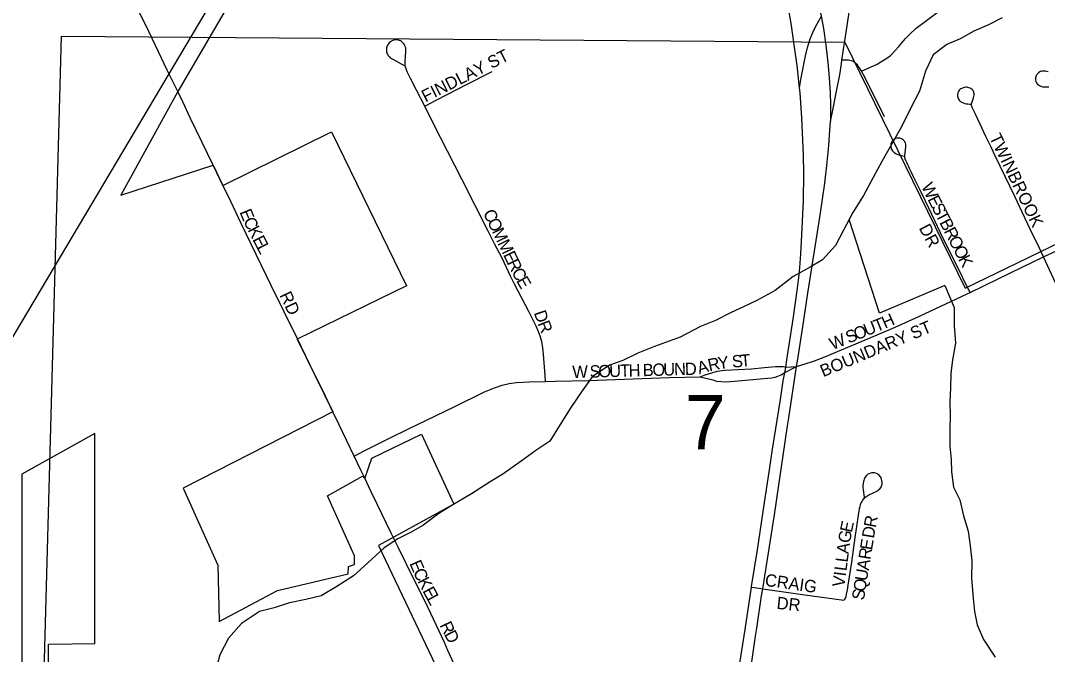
# Model space of a CAD drawing. Extents: x -5.6 to 34, y 0 to 22.
# Drawn here: x 3.152 to 4.822, y 19.057 to 20.089 of the extents above; entities that cross this region are included whole.
import ezdxf

# ---------------------------------------------------------------- set-up
doc = ezdxf.new("R2010")
doc.units = 0
for name, color, linetype in [('GM_X_City_Street', 7, 'Continuous'), ('GM_X_City_Street_Text', 7, 'Continuous'), ('GM_X_Corporation', 7, 'Continuous'), ('GM_X_Minor_River', 7, 'Continuous'), ('GM_X_Rail_Line', 7, 'Continuous'), ('GM_X_Section', 7, 'Continuous'), ('GM_X_Section_Text', 7, 'Continuous'), ('GM_X_State_Route', 7, 'Continuous'), ('GM_X_Township_Road', 7, 'Continuous')]:
    doc.layers.add(name, color=color, linetype=linetype)

msp = doc.modelspace()

# ---------------------------------------------------------------- linework, layer by layer
at = {"layer": 'GM_X_City_Street'}
for points in [[(3.4074, 19.9733), (3.3902, 20.0079), (3.3759, 20.0378), (3.3552, 20.0811), (3.3122, 20.168), (3.2939, 20.2059), (3.2812, 20.2325)], [(4.4957, 20.0768), (4.5106, 20.1745), (4.5139, 20.1982)], [(4.5198, 20.0063), (4.5448, 20.0181), (4.5512, 20.0216), (4.5567, 20.025), (4.5639, 20.03), (4.5671, 20.0325), (4.5698, 20.035), (4.5743, 20.0398), (4.5802, 20.0466), (4.591, 20.0594), (4.5974, 20.066), (4.6087, 20.0762), (4.623, 20.087), (4.6533, 20.1103)], [(4.4187, 19.9793), (4.4216, 19.9958), (4.4283, 20.0312), (4.4317, 20.045), (4.4361, 20.0589), (4.4405, 20.0696), (4.4447, 20.0787), (4.4499, 20.0884), (4.4544, 20.0959)], [(4.4878, 20.0245), (4.4947, 20.0699), (4.4957, 20.0768)], [(3.809, 19.9496), (3.7956, 19.9757), (3.7859, 19.9944), (3.7806, 20.0051), (3.7787, 20.0102), (3.778, 20.0128), (3.7774, 20.0155), (3.777, 20.0188), (3.777, 20.0223), (3.7779, 20.0318), (3.7785, 20.0369), (3.7785, 20.0419), (3.7781, 20.0443), (3.7775, 20.0466), (3.7765, 20.0489), (3.7753, 20.0507), (3.7742, 20.0521), (3.7731, 20.0533), (3.7713, 20.0548), (3.7696, 20.0558), (3.7682, 20.0564), (3.7666, 20.0569), (3.7649, 20.0573), (3.7634, 20.0574), (3.7615, 20.0574), (3.7597, 20.0572), (3.758, 20.0567), (3.7549, 20.0552), (3.752, 20.0531), (3.7497, 20.0505), (3.7486, 20.0489), (3.7479, 20.0474), (3.7473, 20.0459), (3.7469, 20.0442), (3.7466, 20.0424), (3.7466, 20.0407), (3.7468, 20.0388), (3.7471, 20.0373), (3.7476, 20.0356), (3.7483, 20.0341), (3.7492, 20.0326), (3.7504, 20.0311), (3.7516, 20.0298), (3.753, 20.0284), (3.7572, 20.0258), (3.7758, 20.0158)], [(4.4693, 19.9243), (4.4736, 19.9459), (4.4797, 19.9764), (4.4842, 20.0006), (4.4868, 20.0184), (4.4878, 20.0245)], [(4.5198, 20.0063), (4.5191, 20.0076), (4.5164, 20.012), (4.5144, 20.0148), (4.5128, 20.0167), (4.511, 20.0186), (4.5091, 20.0202), (4.507, 20.0216), (4.505, 20.0226), (4.503, 20.0233), (4.5006, 20.0238), (4.4982, 20.0241), (4.4957, 20.0242), (4.4878, 20.0245)], [(3.809, 19.9496), (3.8276, 19.9591), (3.879, 19.9857), (3.919, 20.0059)], [(4.5572, 19.9319), (4.5257, 19.9955), (4.5198, 20.0063)], [(4.823, 20.0051), (4.8211, 20.0058), (4.8189, 20.0063), (4.8165, 20.0066), (4.8148, 20.0066), (4.8131, 20.0063), (4.8109, 20.0057), (4.808, 20.0041), (4.8066, 20.0029), (4.8055, 20.0017), (4.8045, 20.0005), (4.8036, 19.9988), (4.803, 19.9974), (4.8027, 19.9956), (4.8026, 19.9934), (4.8027, 19.9918), (4.8032, 19.9894), (4.8042, 19.9874), (4.8059, 19.9854), (4.8073, 19.9843), (4.8089, 19.9832), (4.8112, 19.982), (4.814, 19.9812), (4.8168, 19.981), (4.8209, 19.9809), (4.8245, 19.9812)], [(4.8157, 19.7041), (4.8089, 19.7184), (4.7946, 19.748), (4.7808, 19.7768), (4.7693, 19.8013), (4.7531, 19.835), (4.7371, 19.8685), (4.7303, 19.8828), (4.722, 19.8999), (4.7125, 19.9203), (4.7051, 19.9362), (4.6992, 19.9482), (4.6988, 19.9496), (4.6987, 19.9513), (4.6987, 19.9535), (4.699, 19.955), (4.7019, 19.9631), (4.7024, 19.9654), (4.7027, 19.9676), (4.7027, 19.9693), (4.7025, 19.971), (4.7021, 19.9725), (4.7018, 19.9736), (4.701, 19.975), (4.7001, 19.9762), (4.6989, 19.9773), (4.6975, 19.9782), (4.6961, 19.9789), (4.6943, 19.9795), (4.6927, 19.98), (4.6906, 19.9802), (4.6891, 19.9802), (4.6873, 19.9799), (4.6839, 19.979), (4.6823, 19.9784), (4.6808, 19.9775), (4.6795, 19.9764), (4.6785, 19.9753), (4.6775, 19.9738), (4.6769, 19.9727), (4.6763, 19.9709), (4.6759, 19.9692), (4.6759, 19.9674), (4.6759, 19.9658), (4.6763, 19.964), (4.6768, 19.9623), (4.6776, 19.9608), (4.6786, 19.9593), (4.6797, 19.9582), (4.681, 19.9569), (4.6824, 19.956), (4.6839, 19.9552), (4.6852, 19.9547), (4.6866, 19.9542), (4.6879, 19.9538), (4.6899, 19.9535), (4.6924, 19.9532), (4.695, 19.953), (4.6965, 19.9529), (4.6978, 19.953)], [(3.4649, 19.8535), (3.4378, 19.9092), (3.428, 19.9296), (3.4154, 19.9564), (3.4074, 19.9733)], [(4.0055, 19.5016), (4.0049, 19.5111), (4.0025, 19.5459), (4.0013, 19.5562), (3.9994, 19.5663), (3.9956, 19.5786), (3.9901, 19.5917), (3.9785, 19.6152), (3.9553, 19.6599), (3.9486, 19.6728), (3.9349, 19.7019), (3.9225, 19.7253), (3.9122, 19.7463), (3.8695, 19.8305), (3.8349, 19.8985), (3.8154, 19.9371), (3.809, 19.9496)], [(4.6962, 19.6464), (4.6905, 19.6579), (4.6777, 19.6837), (4.6532, 19.7332), (4.6292, 19.7837), (4.6165, 19.8096), (4.6043, 19.8346), (4.6003, 19.8428), (4.5978, 19.8479), (4.5937, 19.8569), (4.5912, 19.8624), (4.5906, 19.864), (4.5903, 19.8653), (4.5901, 19.8674), (4.5901, 19.8696), (4.5911, 19.8779), (4.5918, 19.8843), (4.5917, 19.8861), (4.5915, 19.8878), (4.591, 19.8898), (4.5903, 19.8912), (4.5893, 19.8927), (4.5878, 19.8944), (4.5864, 19.8955), (4.5852, 19.8961), (4.5836, 19.8969), (4.5818, 19.8974), (4.58, 19.8974), (4.5783, 19.8974), (4.5769, 19.8972), (4.575, 19.8968), (4.5736, 19.896), (4.5722, 19.8951), (4.5709, 19.894), (4.5696, 19.8928), (4.5687, 19.8914), (4.5679, 19.8899), (4.5674, 19.8884), (4.5671, 19.8865), (4.5671, 19.8848), (4.5672, 19.8834), (4.5676, 19.8815), (4.568, 19.8801), (4.569, 19.8784), (4.5699, 19.8769), (4.5711, 19.8756), (4.5724, 19.8744), (4.5738, 19.8734), (4.5762, 19.8721), (4.5801, 19.8705), (4.5889, 19.8679)], [(3.4806, 19.8205), (3.4756, 19.8309), (3.4649, 19.8535)], [(3.6015, 19.5717), (3.5593, 19.6578), (3.5103, 19.7587), (3.4896, 19.8024), (3.4806, 19.8205)], [(4.8157, 19.7041), (4.8307, 19.7113), (4.8852, 19.7374), (4.9298, 19.7588)], [(4.6962, 19.6464), (4.7632, 19.6789), (4.8157, 19.7041)], [(4.8751, 19.5782), (4.8487, 19.6326), (4.8157, 19.7041)], [(4.4137, 19.5258), (4.4263, 19.5294), (4.4433, 19.5351), (4.4599, 19.5416), (4.5308, 19.5716), (4.5489, 19.5792), (4.5741, 19.5901), (4.6139, 19.6077), (4.6916, 19.6442), (4.6962, 19.6464)], [(3.6596, 19.452), (3.6474, 19.4774), (3.6228, 19.5278), (3.6015, 19.5717)], [(4.2569, 19.5093), (4.2655, 19.5121), (4.2762, 19.5155), (4.2848, 19.518), (4.2974, 19.5197), (4.3186, 19.5208), (4.3408, 19.522), (4.3617, 19.524), (4.3797, 19.5258), (4.3868, 19.526), (4.3921, 19.5256), (4.3965, 19.525)], [(4.2569, 19.5093), (4.2776, 19.5039), (4.2837, 19.5022), (4.2913, 19.5013), (4.299, 19.501), (4.3132, 19.5018), (4.3669, 19.5069), (4.3735, 19.5076), (4.3793, 19.5087), (4.3837, 19.5103), (4.3889, 19.5125), (4.3935, 19.5153), (4.3949, 19.5163)], [(4.3949, 19.5163), (4.4137, 19.5258)], [(4.3965, 19.525), (4.4137, 19.5258)], [(3.6943, 19.3799), (3.7107, 19.3888), (3.7508, 19.4088), (3.7838, 19.4248), (3.7974, 19.4313), (3.8569, 19.4603), (3.9065, 19.4844), (3.9223, 19.4911), (3.9349, 19.4953), (3.9466, 19.498), (3.9585, 19.4997), (3.9796, 19.5008), (4.0055, 19.5016)], [(4.0055, 19.5016), (4.0216, 19.502), (4.0754, 19.5033), (4.2065, 19.5077), (4.2569, 19.5093)], [(3.6943, 19.3799), (3.6692, 19.4319), (3.6596, 19.452)], [(3.7545, 19.2545), (3.7321, 19.3008), (3.7219, 19.3219), (3.711, 19.3452)], [(4.4907, 19.1458), (4.4924, 19.147), (4.4934, 19.1487), (4.4944, 19.1515), (4.4952, 19.1554), (4.4966, 19.1623), (4.4979, 19.1701), (4.5038, 19.2073), (4.5092, 19.2478), (4.5142, 19.2802), (4.5164, 19.2947), (4.5173, 19.2983), (4.5182, 19.3013), (4.5192, 19.3039), (4.5205, 19.3064), (4.5216, 19.3085), (4.5227, 19.3099), (4.5239, 19.3114), (4.5266, 19.314), (4.5315, 19.3172), (4.5375, 19.32), (4.5435, 19.3225), (4.5454, 19.3236), (4.5466, 19.3244), (4.5492, 19.3267), (4.5513, 19.3295), (4.5521, 19.3312), (4.5526, 19.3326), (4.553, 19.3343), (4.5532, 19.3361), (4.5531, 19.3379), (4.5529, 19.3395), (4.552, 19.3429), (4.5513, 19.3445), (4.5503, 19.3461), (4.5482, 19.3489), (4.5468, 19.3502), (4.5455, 19.3511), (4.5425, 19.3524), (4.5407, 19.3528), (4.539, 19.3529), (4.5357, 19.3527), (4.5329, 19.3518), (4.5313, 19.3512), (4.5298, 19.3504), (4.5283, 19.3491), (4.5271, 19.3478), (4.5252, 19.3453), (4.5238, 19.3425), (4.5232, 19.3405), (4.5228, 19.3387), (4.5223, 19.3358), (4.5219, 19.3322), (4.5219, 19.3296), (4.5223, 19.3251), (4.5238, 19.3131)], [(3.879, 18.9927), (3.8717, 19.0094), (3.8625, 19.0295), (3.8469, 19.0638), (3.8411, 19.0766), (3.8096, 19.1434), (3.7914, 19.1799), (3.766, 19.2319), (3.7545, 19.2545)], [(4.3407, 19.1669), (4.3532, 19.165), (4.3591, 19.1642)], [(4.3591, 19.1642), (4.4274, 19.1543), (4.4753, 19.1478), (4.4907, 19.1458)]]:
    msp.add_lwpolyline(points, dxfattribs=at)
at = {"layer": 'GM_X_Corporation'}
for points in [[(3.8378, 20.7105), (3.4074, 19.9733), (3.3145, 19.8045), (3.4649, 19.8535), (3.4806, 19.8205), (3.6573, 19.9077), (3.7796, 19.657), (3.6018, 19.5706), (3.6596, 19.452), (3.4159, 19.328), (3.4725, 19.2028), (3.4746, 19.111), (3.5695, 19.1611), (3.6847, 19.1886), (3.6848, 19.2006), (3.6948, 19.2034), (3.695, 19.2177), (3.6507, 19.3154), (3.7078, 19.3473), (3.7116, 19.3438), (3.7228, 19.3765), (3.8038, 19.4158), (3.8562, 19.3019), (3.7336, 19.2344), (3.8596, 18.9703)], [(3.197, 18.9775), (3.197, 19.074), (3.2726, 19.0753), (3.2725, 19.4168), (3.1535, 19.3507), (3.1536, 18.9777)]]:
    msp.add_lwpolyline(points, dxfattribs=at)
at = {"layer": 'GM_X_Minor_River'}
for points in [[(4.7484, 20.0933), (4.7259, 20.0817), (4.7025, 20.0717), (4.68, 20.0593), (4.6582, 20.0501), (4.6364, 20.0328), (4.6239, 20.0066), (4.6137, 19.9739), (4.5996, 19.9469), (4.5847, 19.9159), (4.569, 19.8881), (4.5525, 19.8596), (4.5384, 19.8334), (4.5227, 19.804), (4.5054, 19.7762), (4.4905, 19.7477), (4.4773, 19.723), (4.4561, 19.6994), (4.4359, 19.6877), (4.4085, 19.6722), (4.3793, 19.6495), (4.3495, 19.6332), (4.3278, 19.6232), (4.3076, 19.6139), (4.2818, 19.6008), (4.2577, 19.5908), (4.2247, 19.5738), (4.1829, 19.5585), (4.1555, 19.5478), (4.1313, 19.5354), (4.1097, 19.5278), (4.0814, 19.5091), (4.065, 19.4861), (4.0469, 19.4592), (4.0296, 19.4315), (4.0124, 19.4045), (3.9897, 19.3889), (3.9662, 19.3717), (3.9363, 19.3506), (3.9153, 19.3382), (3.8854, 19.3187), (3.8523, 19.2993), (3.8321, 19.2868), (3.8062, 19.2672), (3.7861, 19.2556), (3.7651, 19.2455), (3.7433, 19.2307), (3.7165, 19.2064), (3.693, 19.1851), (3.6663, 19.168)], [(4.6551, 19.6578), (4.5487, 19.6127), (4.4995, 19.7648)], [(4.6551, 19.6578), (4.6702, 19.6216), (4.6704, 19.5919), (4.6723, 19.5638), (4.6678, 19.5367), (4.665, 19.5143), (4.6645, 19.491), (4.6633, 19.4678), (4.6637, 19.4461), (4.6633, 19.4245), (4.6635, 19.3964), (4.6655, 19.3747), (4.666, 19.3547), (4.6695, 19.3297), (4.6795, 19.3087), (4.6854, 19.2829), (4.6929, 19.2579), (4.6964, 19.2338), (4.6992, 19.2097), (4.6986, 19.1808), (4.7012, 19.1487), (4.7032, 19.127), (4.7076, 19.1053), (4.7183, 19.0818), (4.7369, 19.0526)], [(3.6663, 19.168), (3.6405, 19.1524), (3.6156, 19.1465), (3.5892, 19.1414), (3.5643, 19.133), (3.5402, 19.127), (3.5111, 19.1075), (3.4899, 19.0839), (3.4758, 19.0569), (3.4698, 19.0345), (3.4687, 19.0128), (3.4687, 18.9907), (3.4698, 18.9471)]]:
    msp.add_lwpolyline(points, dxfattribs=at)
at = {"layer": 'GM_X_Rail_Line'}
msp.add_lwpolyline([(2.1, 17.8198), (3.0599, 19.4414), (3.6284, 20.3994)], dxfattribs=at)
at = {"layer": 'GM_X_Section'}
msp.add_lwpolyline([(3.2183, 20.0634), (4.4924, 20.0538), (4.6881, 19.6534), (5.343, 19.9706), (5.3166, 18.9352), (3.1889, 18.9888)], close=True, dxfattribs=at)
at = {"layer": 'GM_X_State_Route'}
for points in [[(4.4698, 19.9432), (4.4699, 19.9524), (4.469, 19.971), (4.4675, 19.9954), (4.4655, 20.0203), (4.4623, 20.0489), (4.4582, 20.0761), (4.4544, 20.0959), (4.453, 20.1032), (4.4466, 20.1326), (4.4403, 20.1567), (4.4328, 20.1818), (4.4282, 20.1958)], [(4.3142, 18.9953), (4.3302, 19.0979), (4.3407, 19.1669), (4.3408, 19.168), (4.3503, 19.2277), (4.362, 19.3043), (4.3698, 19.3576), (4.375, 19.3914), (4.3876, 19.4719), (4.3922, 19.5024), (4.3949, 19.5163), (4.3958, 19.5211), (4.3965, 19.525), (4.3983, 19.5367), (4.4084, 19.6031), (4.4155, 19.6534), (4.4176, 19.6709), (4.4191, 19.6864), (4.4209, 19.709), (4.4221, 19.729), (4.425, 19.7956), (4.4256, 19.8399), (4.4253, 19.87), (4.4226, 19.9307), (4.4196, 19.9711), (4.4187, 19.9793), (4.4148, 20.0155), (4.4108, 20.0456), (4.4056, 20.0807), (4.3991, 20.1183)], [(4.4013, 19.4422), (4.4137, 19.5258), (4.4152, 19.5348), (4.424, 19.5906), (4.4323, 19.6451), (4.4521, 19.7723), (4.4597, 19.8243), (4.4634, 19.8529), (4.4667, 19.8855), (4.4683, 19.9103), (4.4693, 19.9243), (4.4695, 19.9263), (4.4698, 19.9432)], [(4.3474, 19.0871), (4.3494, 19.1003), (4.3571, 19.1528), (4.3591, 19.1642), (4.3607, 19.1746), (4.3681, 19.2226), (4.3779, 19.2847), (4.3994, 19.4293), (4.4013, 19.4422)], [(4.2978, 18.7592), (4.3024, 18.7894), (4.3155, 18.8724), (4.328, 18.9553), (4.3333, 18.9912), (4.3357, 19.0072), (4.3474, 19.0871)]]:
    msp.add_lwpolyline(points, dxfattribs=at)
at = {"layer": 'GM_X_Township_Road'}
msp.add_lwpolyline([(3.711, 19.3452), (3.7052, 19.3574), (3.6943, 19.3799)], dxfattribs=at)

# ---------------------------------------------------------------- texts
at = {"layer": 'GM_X_City_Street_Text'}
for s, rotation, p in [('FINDLAY ST', 26.8794, (3.8103, 19.9554)), ('TWINBROOK', 295.6645, (4.7271, 19.899)), ('W', 295.1591, (4.6164, 19.8193)), ('E', 297.0781, (4.6265, 19.798)), ('E', 292.3341, (3.5075, 19.7773)), ('C', 295.7829, (3.9034, 19.7759)), ('S', 297.2061, (4.6329, 19.7854)), ('T', 297.1759, (4.6393, 19.7729)), ('C', 295.5728, (3.5134, 19.7632)), ('O', 295.7995, (3.9103, 19.7616)), ('B', 297.1923, (4.6458, 19.7603)), ('K', 297.2497, (3.5205, 19.7483)), ('M', 295.775, (3.9179, 19.7458)), ('DR', 297.8914, (4.6124, 19.7513)), ('R', 297.1923, (4.653, 19.7462)), ('E', 297.3245, (3.5285, 19.7326)), ('M', 295.7973, (3.9271, 19.7267)), ('O', 297.1994, (4.6602, 19.7322)), ('L', 297.2737, (3.535, 19.7201)), ('E', 295.7829, (3.9363, 19.7077)), ('O', 297.1906, (4.6683, 19.7165)), ('R', 295.8008, (3.9424, 19.695)), ('K', 297.1994, (4.6763, 19.7008)), ('C', 297.9569, (3.9497, 19.68)), ('E', 299.6616, (3.9574, 19.6655)), ('RD', 295.2073, (3.5725, 19.6421)), ('D', 288.9394, (3.9863, 19.6134)), ('H', 23.8358, (4.5578, 19.5871)), ('R', 291.5444, (3.9923, 19.5959)), ('BOUNDARY ST', 22.6679, (4.4573, 19.5083)), ('U', 22.0729, (4.5278, 19.5749)), ('T', 22.0723, (4.5441, 19.5815)), ('W', 22.0793, (4.4723, 19.5524)), ('S', 22.0723, (4.4985, 19.563)), ('O', 22.0729, (4.5115, 19.5683)), ('T', 4.9944, (4.3236, 19.525)), ('O', 1.5255, (4.0917, 19.5081)), ('U', 1.5255, (4.1093, 19.5085)), ('T', 1.5031, (4.1269, 19.509)), ('H', 1.5255, (4.141, 19.5094)), ('B', 1.5256, (4.1639, 19.51)), ('O', 1.5255, (4.1797, 19.5104)), ('U', 1.508, (4.1973, 19.5109)), ('N', 1.5255, (4.2149, 19.5114)), ('D', 1.5255, (4.2325, 19.5118)), ('A', 15.8494, (4.2554, 19.5131)), ('R', 12.5815, (4.2721, 19.5178)), ('Y', 6.9244, (4.287, 19.5212)), ('S', 4.982, (4.3096, 19.5238)), ('W', 1.53, (4.0495, 19.507)), ('S', 1.5009, (4.0776, 19.5077)), ('R', 79.2998, (4.5426, 19.2626)), ('E', 77.6934, (4.5037, 19.2546)), ('D', 80.6024, (4.5397, 19.2453)), ('G', 80.4478, (4.5009, 19.2375)), ('E', 80.7802, (4.5366, 19.2262)), ('A', 82.6581, (4.4986, 19.2202)), ('R', 80.8052, (4.5341, 19.2106)), ('E', 293.3134, (3.7838, 19.2055)), ('L', 82.6852, (4.4969, 19.2063)), ('C', 294.7966, (3.7896, 19.192)), ('L', 82.6955, (4.4951, 19.1923)), ('U', 80.782, (4.5284, 19.1758)), ('A', 80.7861, (4.5313, 19.1932)), ('K', 297.8445, (3.7967, 19.1766)), ('CRAIG', 352.0557, (4.3616, 19.169)), ('V', 82.6798, (4.4917, 19.1661)), ('I', 82.6364, (4.4939, 19.1836)), ('Q', 80.7958, (4.5256, 19.1585)), ('E', 298.1989, (3.805, 19.1609)), ('S', 80.7802, (4.5234, 19.1446)), ('L', 298.1657, (3.8117, 19.1485)), ('DR', 353.9832, (4.3808, 19.1316)), ('R', 295.3162, (3.833, 19.1052)), ('D', 297.4652, (3.8401, 19.0902))]:
    msp.add_text(s, height=0.02, rotation=rotation, dxfattribs=at).set_placement(p)
at = {"layer": 'GM_X_Section_Text'}
msp.add_text('7', height=0.0884, rotation=0, dxfattribs=at).set_placement((4.2326, 19.3909))

doc.saveas('drawing.dxf')
